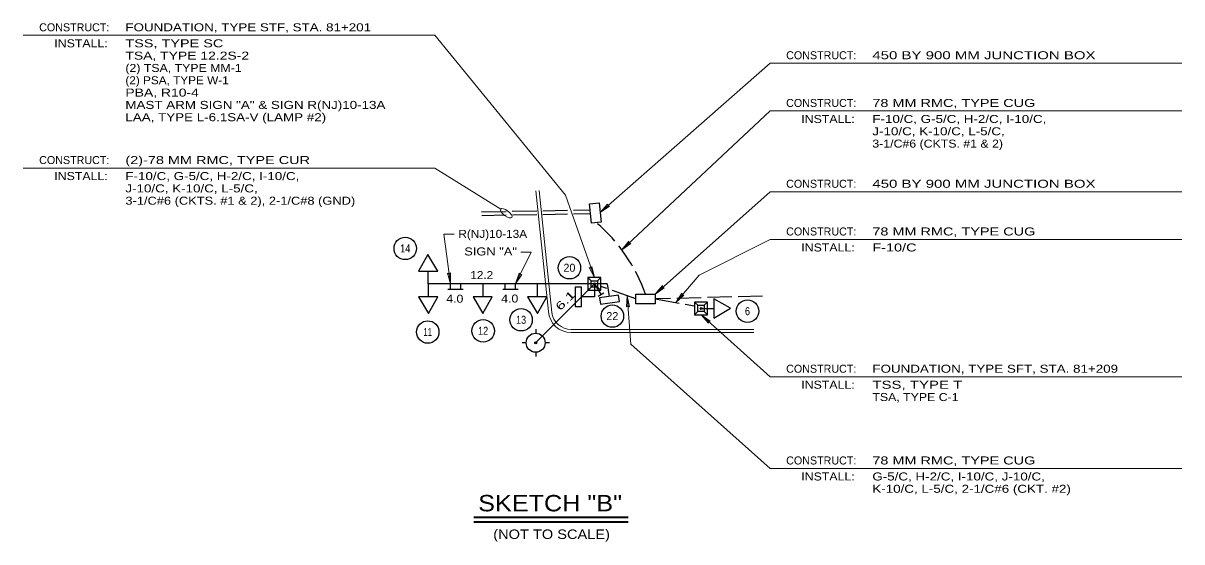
# Model space of a CAD drawing. Extents: x 168203 to 169864, y 223196 to 223870.
# Drawn here: x 168653.1 to 168738.1, y 223261.7 to 223299.8 of the extents above; entities that cross this region are included whole.
import ezdxf
from ezdxf.enums import TextEntityAlignment as Align

# ---------------------------------------------------------------- set-up
doc = ezdxf.new("R2010")
doc.units = 0
doc.header["$LTSCALE"] = 0.3
doc.header["$PDMODE"] = 32
doc.header["$PDSIZE"] = 0.15
doc.linetypes.add('LONG_DASHED', pattern=[7.5, 6, -1.5])
for name, color, linetype, lineweight in [('1', 7, 'Continuous', 13), ('10', 7, 'Continuous', 13), ('32', 7, 'Continuous', 25), ('4', 7, 'Continuous', 25), ('6', 7, 'Continuous', 25), ('8', 7, 'Continuous', 25), ('9', 7, 'Continuous', 13)]:
    doc.layers.add(name, color=color, linetype=linetype, lineweight=lineweight)

msp = doc.modelspace()

# ---------------------------------------------------------------- linework, layer by layer
at = {"layer": '1'}
for p, q in [((168691.6329, 223278.6176), (168690.7124, 223287.4748)), ((168691.8712, 223278.5504), (168690.9412, 223287.4985)), ((168706.7124, 223277.3058), (168693.3035, 223277.3058)), ((168706.7124, 223277.0758), (168693.2955, 223277.0758))]:
    msp.add_line(p, q, dxfattribs=at)
for radius, start, end in [(1.6673, 184.13349, 270.00005), (1.4373, 187.706, 270.3211)]:
    msp.add_arc((168693.2955, 223278.7431), radius, start, end, dxfattribs=at)
at = {"layer": '10'}
for p, q in [((168683.2943, 223298.8853), (168653.0865, 223298.8853)), ((168695.4269, 223285.88), (168707.8988, 223296.8353)), ((168738.1066, 223296.8353), (168707.8988, 223296.8353)), ((168697.0171, 223283.1354), (168707.8988, 223293.3353)), ((168738.1066, 223293.3353), (168707.8988, 223293.3353)), ((168683.2943, 223289.1467), (168653.0865, 223289.1467)), ((168688.1264, 223286.1381), (168683.2943, 223289.1467)), ((168699.4522, 223279.9), (168707.8988, 223287.408)), ((168738.1066, 223287.408), (168707.8988, 223287.408)), ((168738.1066, 223283.908), (168707.8988, 223283.908)), ((168702.828, 223278.3732), (168707.8988, 223273.8389)), ((168738.1066, 223273.8389), (168707.8988, 223273.8389)), ((168738.1066, 223267.1093), (168707.8988, 223267.1093))]:
    msp.add_line(p, q, dxfattribs=at)
for points in [[(168695, 223281.113), (168692.8752, 223287.1498), (168683.2943, 223298.8853)], [(168700.9676, 223279.2766), (168702.6968, 223281.289), (168707.8988, 223283.908)], [(168697.3963, 223279.7724), (168697.6767, 223276.232), (168707.8988, 223267.1093)]]:
    msp.add_lwpolyline(points, dxfattribs=at)
for points in [[(168696.1035, 223286.3421), (168695.4269, 223285.88), (168695.9664, 223286.4982), (168695.9768, 223286.363)], [(168697.6785, 223283.6191), (168697.0171, 223283.1354), (168697.5363, 223283.7707), (168697.5511, 223283.6359)], [(168694.8237, 223281.9132), (168695, 223281.113), (168694.6277, 223281.8442), (168694.757, 223281.8034)], [(168700.1261, 223280.366), (168699.4522, 223279.9), (168699.9881, 223280.5213), (168699.9992, 223280.3862)], [(168701.573, 223279.8287), (168700.9676, 223279.2766), (168701.4154, 223279.9641), (168701.4446, 223279.8317)], [(168697.3614, 223278.9538), (168697.3963, 223279.7724), (168697.5686, 223278.9702), (168697.4541, 223279.0428)], [(168703.368, 223277.757), (168702.828, 223278.3732), (168703.5065, 223277.9119), (168703.3736, 223277.8853)]]:
    msp.add_lwpolyline(points, close=True, dxfattribs=at)
msp.add_ellipse((168688.5362, 223285.8283), major_axis=(-0.4098, 0.3098), ratio=0.392166, dxfattribs=at)
at = {"layer": '32', "lineweight": 13}
for p, q in [((168683.9455, 223284.304), (168684.7042, 223284.304)), ((168684.4429, 223280.643), (168683.9455, 223284.304)), ((168689.2219, 223280.6438), (168690.3583, 223282.9722)), ((168689.5996, 223282.9722), (168690.3583, 223282.9722))]:
    msp.add_line(p, q, dxfattribs=at)
at = {"layer": '32'}
for p, q in [((168682.8045, 223280.6431), (168682.8045, 223279.7033)), ((168684.4429, 223280.2635), (168684.4429, 223280.643)), ((168685.2019, 223280.2635), (168685.2019, 223280.643)), ((168686.8045, 223280.6431), (168686.8045, 223279.7033)), ((168688.4629, 223280.2643), (168688.4629, 223280.6438)), ((168689.2219, 223280.2643), (168689.2219, 223280.6438)), ((168695.0045, 223280.6431), (168690.6912, 223276.3297)), ((168690.8045, 223280.6431), (168690.8045, 223279.7033)), ((168695.0045, 223280.6431), (168695.0045, 223279.7033)), ((168695.9443, 223280.6431), (168695.0045, 223280.6431)), ((168695.0045, 223280.6431), (168695.4929, 223279.8402)), ((168695.9443, 223280.6431), (168696.0776, 223279.7128)), ((168684.2531, 223280.2635), (168685.3826, 223280.2635)), ((168688.2731, 223280.2643), (168689.4026, 223280.2643)), ((168695.6936, 223279.9622), (168695.2844, 223279.7134)), ((168695.0045, 223279.7033), (168694.0647, 223279.7033)), ((168702.8325, 223278.8431), (168703.7723, 223278.8431))]:
    msp.add_line(p, q, dxfattribs=at)
for points in [[(168682.7864, 223282.8027), (168682.0997, 223281.5829), (168682.8045, 223281.5829), (168683.5093, 223281.5829)], [(168693.5949, 223280.4172), (168693.5949, 223278.9985), (168694.0647, 223278.9985), (168694.0647, 223280.4172)], [(168695.4376, 223279.1465), (168696.8419, 223279.3477), (168696.7753, 223279.8128), (168695.3709, 223279.6115)], [(168682.8226, 223278.4835), (168683.5093, 223279.7033), (168682.8045, 223279.7033), (168682.0997, 223279.7033)], [(168686.8226, 223278.4835), (168687.5093, 223279.7033), (168686.8045, 223279.7033), (168686.0997, 223279.7033)], [(168690.8226, 223278.4835), (168691.5093, 223279.7033), (168690.8045, 223279.7033), (168690.0997, 223279.7033)], [(168704.9921, 223278.8612), (168703.7723, 223279.5479), (168703.7723, 223278.8431), (168703.7723, 223278.1383)]]:
    msp.add_lwpolyline(points, close=True, dxfattribs=at)
msp.add_lwpolyline([(168695.0045, 223280.6431), (168682.8045, 223280.6431), (168682.8045, 223281.5829)], dxfattribs=at)
at = {"layer": '32', "lineweight": 13}
for points in [[(168684.4319, 223281.4623), (168684.4429, 223280.643), (168684.226, 223281.4343), (168684.3444, 223281.3682)], [(168689.6679, 223281.3311), (168689.2219, 223280.6438), (168689.4812, 223281.4222), (168689.5429, 223281.3015)]]:
    msp.add_lwpolyline(points, close=True, dxfattribs=at)
at = {"layer": '32'}
for centre in [(168681.124, 223283.2489), (168693.1689, 223281.8297), (168696.3185, 223278.2827), (168706.2354, 223278.644), (168689.6214, 223278.0132), (168682.7725, 223277.116), (168686.8368, 223277.2049)]:
    msp.add_circle(centre, 0.8236, dxfattribs=at)
at = {"layer": '4'}
for p, q in [((168694.5301, 223281.113), (168694.7651, 223280.878)), ((168695.4699, 223281.113), (168695.2349, 223280.878)), ((168694.5301, 223280.1732), (168694.7651, 223280.4082)), ((168695.4699, 223280.1732), (168695.2349, 223280.4082)), ((168702.3581, 223279.313), (168702.5931, 223279.078)), ((168703.2979, 223279.313), (168703.0629, 223279.078)), ((168702.3581, 223278.3732), (168702.5931, 223278.6082)), ((168703.2979, 223278.3732), (168703.0629, 223278.6082))]:
    msp.add_line(p, q, dxfattribs=at)
for points in [[(168694.5301, 223281.113), (168694.5301, 223280.1732), (168695.4699, 223280.1732), (168695.4699, 223281.113)], [(168694.7651, 223280.878), (168695.2349, 223280.878), (168695.2349, 223280.4082), (168694.7651, 223280.4082)], [(168702.3581, 223279.313), (168702.3581, 223278.3732), (168703.2979, 223278.3732), (168703.2979, 223279.313)], [(168702.5931, 223279.078), (168703.0629, 223279.078), (168703.0629, 223278.6082), (168702.5931, 223278.6082)]]:
    msp.add_lwpolyline(points, close=True, dxfattribs=at)
for p in [(168695.009, 223280.6431), (168702.837, 223278.8431)]:
    msp.add_point(p, dxfattribs=at)
at = {"layer": '6', "linetype": 'LONG_DASHED'}
for p, q in [((168686.7262, 223285.9341), (168694.6895, 223286.0701)), ((168686.7307, 223285.6699), (168694.7169, 223285.8063)), ((168698.0335, 223279.5431), (168695.4699, 223280.4655)), ((168707.3422, 223279.7482), (168699.4522, 223279.5431)), ((168699.4522, 223279.5431), (168702.3581, 223279.0321))]:
    msp.add_line(p, q, dxfattribs=at)
at = {"layer": '6'}
for points in [[(168695.5002, 223285.1745), (168694.7902, 223285.1007), (168694.6436, 223286.5118), (168695.3536, 223286.5856)], [(168698.0335, 223279.1862), (168698.0335, 223279.9), (168699.4522, 223279.9), (168699.4522, 223279.1862)]]:
    msp.add_lwpolyline(points, close=True, dxfattribs=at)
at = {"layer": '6', "linetype": 'LONG_DASHED'}
msp.add_arc((168687.1701, 223275.8053), 12.2757, 19.48491, 49.48384, dxfattribs=at)
at = {"layer": '8'}
for p, q in [((168690.7008, 223277.3168), (168690.7072, 223277.0293)), ((168689.9915, 223276.3265), (168689.7041, 223276.3201)), ((168690.7072, 223275.6365), (168690.7008, 223275.3233)), ((168691.704, 223276.3265), (168691.3845, 223276.3265))]:
    msp.add_line(p, q, dxfattribs=at)
msp.add_circle((168690.6912, 223276.3297), 0.6965, dxfattribs=at)
msp.add_point((168690.6944, 223276.3265), dxfattribs=at)
at = {"layer": '9', "lineweight": 35}
for p, q in [((168686.1624, 223263.5264), (168697.4782, 223263.5264)), ((168686.1624, 223263.179), (168697.4782, 223263.179))]:
    msp.add_line(p, q, dxfattribs=at)

# ---------------------------------------------------------------- texts
at = {"layer": '10'}
for p in [(168654.2612, 223299.1745), (168709.0735, 223297.1245), (168709.0735, 223293.6245), (168654.2612, 223289.4359), (168709.0735, 223287.6972), (168709.0735, 223284.1972), (168709.0735, 223274.1281), (168709.0735, 223267.3985)]:
    msp.add_text('CONSTRUCT:', height=0.5873, dxfattribs=at).set_placement(p)
for s, width, p in [('FOUNDATION, TYPE STF, STA. 81+201    ', 1.25, (168660.5865, 223299.1745)), ('TSS, TYPE SC                         ', 1.35, (168660.5865, 223297.9998)), ('TSA, TYPE 12.2S-2                    ', 1.3, (168660.5865, 223297.0961)), ('450 BY 900 MM JUNCTION BOX           ', 1.4, (168715.3988, 223297.1245)), ('(2) TSA, TYPE MM-1                   ', 1.15, (168660.5865, 223296.1925)), ('(2) PSA, TYPE W-1                    ', 1.1, (168660.5865, 223295.2889)), ('PBA, R10-4                           ', 1.3, (168660.5865, 223294.3853)), ('MAST ARM SIGN "A" & SIGN R(NJ)10-13A ', 1.25, (168660.5865, 223293.4817)), ('78 MM RMC, TYPE CUG                  ', 1.35, (168715.3988, 223293.6245)), ('LAA, TYPE L-6.1SA-V (LAMP #2)   ', 1.25, (168660.5865, 223292.5781)), ('F-10/C, G-5/C, H-2/C, I-10/C,', 1.25, (168715.3988, 223292.4498)), ('J-10/C, K-10/C, L-5/C,        ', 1.25, (168715.3988, 223291.5461)), ('3-1/C#6 (CKTS. #1 & 2)     ', 1.15, (168715.3988, 223290.6425)), ('(2)-78 MM RMC, TYPE CUR                ', 1.35, (168660.5865, 223289.4359)), ('F-10/C, G-5/C, H-2/C, I-10/C,', 1.25, (168660.5865, 223288.2612)), ('450 BY 900 MM JUNCTION BOX           ', 1.4, (168715.3988, 223287.6972)), ('J-10/C, K-10/C, L-5/C,        ', 1.25, (168660.5865, 223287.3575)), ('3-1/C#6 (CKTS. #1 & 2), 2-1/C#8 (GND) ', 1.2, (168660.5865, 223286.4539)), ('78 MM RMC, TYPE CUG                  ', 1.35, (168715.3988, 223284.1972)), ('F-10/C                     ', 1.35, (168715.3988, 223283.0225)), ('FOUNDATION, TYPE SFT, STA. 81+209    ', 1.25, (168715.3988, 223274.1281)), ('TSS, TYPE T                          ', 1.4, (168715.3988, 223272.9534)), ('TSA, TYPE C-1                        ', 1.15, (168715.3988, 223272.0497)), ('78 MM RMC, TYPE CUG                  ', 1.35, (168715.3988, 223267.3985)), ('G-5/C, H-2/C, I-10/C, J-10/C, ', 1.25, (168715.3988, 223266.2238)), ('K-10/C, L-5/C, 2-1/C#6 (CKT. #2) ', 1.25, (168715.3988, 223265.3201))]:
    msp.add_text(s, height=0.5873, dxfattribs=dict(at, width=width)).set_placement(p)
at = {"layer": '10', "width": 1.15}
for p in [(168659.2884, 223297.9998), (168714.1007, 223292.4498), (168659.2884, 223288.2612), (168714.1007, 223283.0225), (168714.1007, 223272.9534), (168714.1007, 223266.2238)]:
    msp.add_text('INSTALL:', height=0.5873, dxfattribs=at).set_placement(p, align=Align.RIGHT)
at = {"layer": '32'}
for s, width, p in [('R(NJ)10-13A', 1.1, (168687.5425, 223284.0217)), ('14', 0.85, (168681.124, 223282.9553)), ('SIGN "A"', 1.2, (168687.3838, 223282.7309)), ('12.2', 1.1, (168686.7348, 223280.9992)), ('4.0', 1.15, (168684.7578, 223279.2636)), ('4.0', 1.15, (168688.7922, 223279.2783)), ('6', 0.85, (168706.2354, 223278.3504)), ('13', 0.85, (168689.6214, 223277.7196)), ('11', 0.7, (168682.7725, 223276.8224)), ('12', 0.85, (168686.8368, 223276.9113))]:
    msp.add_text(s, height=0.5873, dxfattribs=dict(at, width=width)).set_placement(p, align=Align.CENTER)
for s, p in [('20', (168693.169, 223281.5361)), ('22', (168696.3186, 223277.9891))]:
    msp.add_text(s, height=0.5873, dxfattribs=at).set_placement(p, align=Align.CENTER)
at = {"layer": '32', "width": 1.5}
msp.add_text('6.1', height=0.5873, rotation=45.001, dxfattribs=at).set_placement((168693.0752, 223279.2184), align=Align.CENTER)
at = {"layer": '9', "width": 1.15}
msp.add_text('SKETCH "B"', height=1.202, dxfattribs=at).set_placement((168691.7536, 223263.9601), align=Align.CENTER)
msp.add_text('(NOT TO SCALE)', height=0.6958, dxfattribs=at).set_placement((168687.5805, 223261.9335))

doc.saveas('drawing.dxf')
